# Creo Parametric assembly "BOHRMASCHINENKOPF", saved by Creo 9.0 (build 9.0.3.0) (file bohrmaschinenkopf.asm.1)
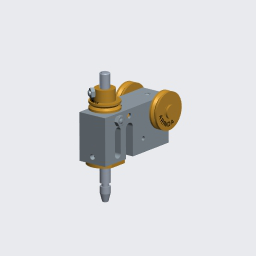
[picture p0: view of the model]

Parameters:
  ERSTELLER = "ARINDA"
  BENENNUNG = "XXX"
  TEILETYP = "K"

Other parameters: MASSE

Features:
  1. coordinate system
  2. datum plane "A_RECHTS_Y-Z"
  3. datum plane "A_OBEN_X-Z"
  4. datum plane "A_VORNE_X-Y"
  5. datum axis
  6. datum axis
  7. datum axis
  8. datum point "APNT0"
  9. component "GETRIEBEGEHÄUSE"
  10. component "UMLENKROLLE-ACHSE"
  11. component "ISO7434_M4X4"
  12. component "UMLENKROLLE"
  13. component "UMLENKROLLE"
  14. component "SPINDELFÜHRUNG"
  15. component "ISO7434_M4X4"
  16. component "ISO2338"
  17. component "UMLENKROLLE-SPINDEL"
  18. component "ISO7435", "ISO7435_M3.PRT"
  19. component "ISO4032_1", "ISO4032_1M3.PRT"
  20. component "BOHRSPINDEL"
  21. component "ISO7435", "ISO7435_M3.PRT"
  22. component "ISO4032_1", "ISO4032_1M3.PRT"

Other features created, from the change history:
  planar section "XSEC0001"
  planar section "B"

Other named items: AA_X, AA_Y, AA_Z, ACS0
